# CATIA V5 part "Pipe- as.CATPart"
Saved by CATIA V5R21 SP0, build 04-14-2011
Part number: Pipe- as
Bounding box of the stored display mesh (mm): x -9 to 9, y 0 to 27, z -9 to 9
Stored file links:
  C:\Users\Administrator\Desktop\catia 자격증 시험예제파일\sample6\Pipe- as.CATPart
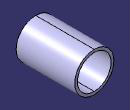
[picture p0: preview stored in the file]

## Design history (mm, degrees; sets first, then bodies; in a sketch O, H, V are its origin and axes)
Body1 (main body)
  Sketch1 on zx-plane, origin (0, 0, 0), H (0, 0, 1), V (1, 0, 0)
    circle A1 centre (0, 0) radius 9
    circle A2 centre (0, 0) radius 7.75
    radius A1 = 9
    radius A2 = 7.75
  Pad1: profile Sketch1, direction (0, 1, 0), length 27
